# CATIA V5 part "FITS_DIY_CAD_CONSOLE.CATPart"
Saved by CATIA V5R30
Part number: FITS_DIY_CAD
Revision: 1
Definition: FITS_DIY_CAD
Nomenclature: FITS_DIY_CAD
Property "C3PNG_QC_Identifier": "0"
Property "C3PNG_QC_ProfileVersion": "QC_RUN_ABSENT"
Property "C3PNG_QC_ModelAssessment": "QC_RUN_ABSENT"
Property "C3PNG_ItemName": "console bin study - bin"
Property "EBS_ItemRevName": "console bin study - bin"
Bounding box of the stored display mesh (mm): x 3358.75 to 3389.83, y -64.02 to 64.02, z 662.297 to 760
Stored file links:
  C:\Users\gmarsh66\Desktop\misc me\ford\fits accessories\misc\FITS_DIY_CAD_console_revc.CATPart
  C:\Users\Public\NG\tmp\tcic\catuii\FNA7697309.CATProduct
  C:\Users\Public\NG\tmp\tcic\catuii\LFC\LFC_1_FNA8223815.CATPart
  C:\Users\Public\NG\tmp\tcic\catuii\NZ6B-E04584-A.CATPart
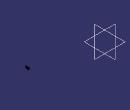
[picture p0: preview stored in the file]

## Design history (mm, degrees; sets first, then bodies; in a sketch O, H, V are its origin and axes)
TTRSSet1
f4a2d38f3ddc11d3a929006094b99c4b_11 "CATTPSSet"
Set1
  DatumSurface1 to DatumSurface11
  Plane1: type Offset, RefPlane xy-plane, Offset 760
  MultiSel1
Body1 (main body)
Body2 "square version cover updated.1\\MANIFOLD_SOLID_BREP #11337"
  Solid1: solid without history
  Split1: SplitPlane Plane1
